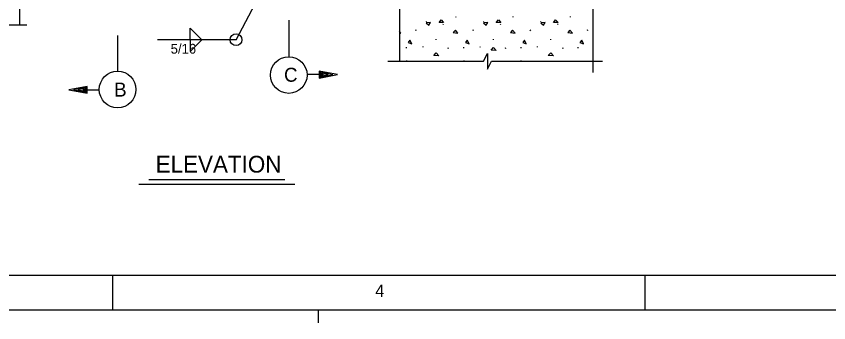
# Model space of a CAD drawing. Extents: x 0.1 to 13.5, y 0.1 to 9.5.
# Drawn here: x 2.665 to 6.543, y 0.064 to 1.527 of the extents above; entities that cross this region are included whole.
import ezdxf

# ---------------------------------------------------------------- set-up
doc = ezdxf.new("R2010")
doc.units = 0
for name, color, linetype in [('Level 1', 7, 'Continuous'), ('Level 10', 7, 'Continuous'), ('Level 13', 7, 'Continuous'), ('Level 2', 7, 'Continuous'), ('Level 25', 7, 'Continuous'), ('Level 3', 7, 'Continuous'), ('Level 4', 7, 'Continuous')]:
    doc.layers.add(name, color=color, linetype=linetype)

msp = doc.modelspace()

# ---------------------------------------------------------------- linework, layer by layer
at = {"layer": 'Level 1'}
for p, q in [((3.1238, 0.2903), (3.1238, 0.1236)), ((5.6654, 0.2903), (5.6654, 0.1236))]:
    msp.add_line(p, q, dxfattribs=at)
for points in [[(0.1238, 9.4569), (13.4571, 9.4569), (13.4571, 0.1236), (0.1238, 0.1236)], [(0.6238, 9.2903), (13.2904, 9.2903), (13.2904, 0.2903), (0.6238, 0.2903)]]:
    msp.add_lwpolyline(points, close=True, dxfattribs=at)
at = {"layer": 'Level 10'}
for p, q in [((4.7633, 1.5225), (4.7638, 1.5262)), ((5.0366, 1.5225), (5.0371, 1.5262)), ((5.3099, 1.5225), (5.3104, 1.5262)), ((4.6225, 1.4997), (4.6228, 1.5025)), ((4.7023, 1.4872), (4.7042, 1.4903)), ((4.8958, 1.4997), (4.8961, 1.5025)), ((4.9756, 1.4872), (4.9775, 1.4903)), ((5.1691, 1.4997), (5.1694, 1.5025)), ((5.2489, 1.4872), (5.2508, 1.4903)), ((4.5736, 1.458), (4.5719, 1.4613)), ((4.8469, 1.458), (4.8452, 1.4613)), ((5.1202, 1.458), (5.1185, 1.4613)), ((5.3935, 1.458), (5.3918, 1.4613)), ((4.6698, 1.4144), (4.6696, 1.4175)), ((4.9431, 1.4144), (4.9429, 1.4175)), ((5.2164, 1.4144), (5.2162, 1.4175)), ((4.5274, 1.3749), (4.5274, 1.3787)), ((4.6063, 1.3793), (4.6068, 1.3822)), ((4.728, 1.3719), (4.7269, 1.3757)), ((4.8008, 1.3749), (4.8008, 1.3787)), ((4.8796, 1.3793), (4.8801, 1.3822)), ((5.0013, 1.3719), (5.0003, 1.3757)), ((5.0741, 1.3749), (5.0741, 1.3787)), ((5.1529, 1.3793), (5.1534, 1.3822)), ((5.2746, 1.3719), (5.2736, 1.3757)), ((5.3474, 1.3749), (5.3474, 1.3787)), ((4.5288, 1.3127), (4.5288, 1.3162)), ((4.8021, 1.3127), (4.8021, 1.3162))]:
    msp.add_line(p, q, dxfattribs=at)
for points in [[(4.6216, 1.4957), (4.6349, 1.4838), (4.642, 1.4971)], [(4.6827, 1.4971), (4.6928, 1.5104), (4.7041, 1.4976)], [(4.8949, 1.4957), (4.9082, 1.4838), (4.9153, 1.4971)], [(4.956, 1.4971), (4.9661, 1.5104), (4.9774, 1.4976)], [(5.1682, 1.4957), (5.1815, 1.4838), (5.1886, 1.4971)], [(5.2293, 1.4971), (5.2394, 1.5104), (5.2507, 1.4976)], [(4.7732, 1.4467), (4.7608, 1.461), (4.7509, 1.4492)], [(5.0465, 1.4467), (5.0341, 1.461), (5.0242, 1.4492)], [(5.3198, 1.4467), (5.3074, 1.461), (5.2975, 1.4492)], [(4.5356, 1.4012), (4.5526, 1.3945), (4.5436, 1.413)], [(4.8089, 1.4012), (4.8259, 1.3945), (4.8169, 1.413)], [(5.0822, 1.4012), (5.0993, 1.3945), (5.0903, 1.413)], [(5.3555, 1.4012), (5.3726, 1.3945), (5.3636, 1.413)], [(4.9309, 1.3653), (4.9428, 1.3781), (4.9555, 1.3639)], [(4.6576, 1.3393), (4.6694, 1.3522), (4.6822, 1.338)], [(5.2042, 1.3393), (5.2161, 1.3522), (5.2288, 1.338)]]:
    msp.add_lwpolyline(points, close=True, dxfattribs=at)
for points in [[(4.4999, 1.4467), (4.4935, 1.454)], [(4.4935, 1.4474), (4.4999, 1.4467)], [(5.0754, 1.3135), (5.0754, 1.3162)]]:
    msp.add_lwpolyline(points, dxfattribs=at)
at = {"layer": 'Level 13'}
msp.add_lwpolyline([(4.8954, 1.312), (4.914, 1.3495), (4.914, 1.2746), (4.9327, 1.312)], dxfattribs=at)
at = {"layer": 'Level 2'}
for p, q in [((2.681, 2.3997), (2.681, 1.4864)), ((4.4935, 2.3997), (4.4935, 1.312)), ((5.4175, 2.0093), (5.4175, 1.2591)), ((2.4932, 1.4864), (2.7152, 1.4864)), ((4.4382, 1.312), (4.8954, 1.312)), ((4.9327, 1.312), (5.4632, 1.312)), ((4.9514, 1.312), (5.4632, 1.312)), ((4.1074, 0.0643), (4.1074, 0.1268))]:
    msp.add_line(p, q, dxfattribs=at)
at = {"layer": 'Level 25'}
msp.add_line((3.7141, 1.4148), (4.0204, 1.9954), dxfattribs=at)
at = {"layer": 'Level 3'}
for p, q in [((3.9654, 1.5076), (3.9654, 1.3355)), ((3.1486, 1.435), (3.1486, 1.2629)), ((4.1112, 1.2481), (4.0529, 1.2481)), ((3.0028, 1.1755), (3.0611, 1.1755)), ((3.2985, 0.7471), (3.9469, 0.7471)), ((3.2496, 0.7263), (3.9947, 0.7263))]:
    msp.add_line(p, q, dxfattribs=at)
for points in [[(4.1112, 1.2359), (4.1112, 1.2315), (4.1987, 1.2481), (4.1112, 1.2644), (4.1112, 1.2359), (4.1764, 1.2478), (4.1154, 1.2595), (4.1154, 1.2407), (4.1544, 1.2478), (4.1195, 1.2544), (4.1195, 1.2456), (4.1321, 1.2478), (4.1238, 1.2494)], [(3.0028, 1.1878), (3.0028, 1.1921), (2.9153, 1.1755), (3.0028, 1.1592), (3.0028, 1.1878), (2.9376, 1.1758), (2.9986, 1.1641), (2.9986, 1.183), (2.9596, 1.1758), (2.9945, 1.1693), (2.9945, 1.178), (2.982, 1.1758), (2.9903, 1.1742)]]:
    msp.add_lwpolyline(points, dxfattribs=at)
for centre in [(3.9654, 1.2464), (3.1487, 1.1772)]:
    msp.add_circle(centre, 0.0875, dxfattribs=at)
at = {"layer": 'Level 4'}
for p, q in [((3.4945, 1.4704), (3.5503, 1.4146)), ((3.4945, 1.4142), (3.4945, 1.4704)), ((3.7141, 1.4148), (3.339, 1.4148)), ((3.4945, 1.4153), (3.4945, 1.3591)), ((3.4945, 1.3591), (3.5503, 1.415))]:
    msp.add_line(p, q, dxfattribs=at)
msp.add_circle((3.7141, 1.4148), 0.0281, dxfattribs=at)

# ---------------------------------------------------------------- texts
at = {"layer": 'Level 1'}
msp.add_text('4', height=0.0584, dxfattribs=at).set_placement((4.3782, 0.1876))
at = {"layer": 'Level 3'}
for s, height, p in [('5/16', 0.04667, (3.4019, 1.3484)), ('C', 0.0667, (3.9431, 1.2143)), ('B', 0.0667, (3.1323, 1.1435)), ('ELEVATION', 0.08, (3.3303, 0.7808))]:
    msp.add_text(s, height=height, dxfattribs=at).set_placement(p)

doc.saveas('drawing.dxf')
